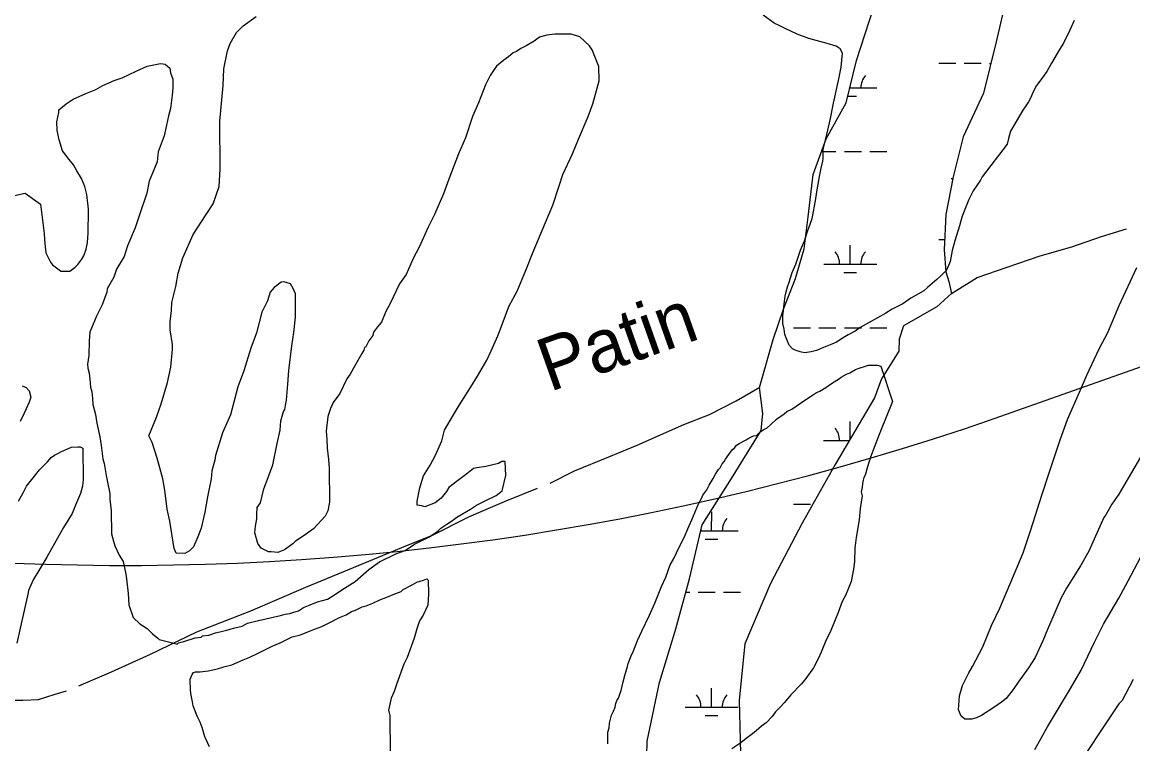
# Model space of a CAD drawing. Extents: x 3250478 to 3288318, y 788638 to 816472.
# Drawn here: x 3266413 to 3268510, y 804468 to 805829 of the extents above; entities that cross this region are included whole.
import ezdxf

# ---------------------------------------------------------------- set-up
doc = ezdxf.new("R2010")
doc.units = 0
for name, color, linetype in [('V-RIVR-IDEN', 7, 'Continuous'), ('V-ROAD-CNTR', 7, 'Continuous'), ('V-SITE-VEGE', 7, 'Continuous'), ('V-TOPO-SHOR', 7, 'Continuous'), ('V-WETL-SWMP', 7, 'Continuous')]:
    doc.layers.add(name, color=color, linetype=linetype)

msp = doc.modelspace()

# ---------------------------------------------------------------- linework, layer by layer
at = {"layer": 'V-ROAD-CNTR'}
msp.add_lwpolyline([(3268249.8, 805082), (3271535.1, 806242), (3280405.6, 809312.9)], dxfattribs=at)
msp.add_arc((3266606.2, 809804.1), 5000, 244.6063, 289.1908, dxfattribs=at)
at = {"layer": 'V-SITE-VEGE'}
for points in [[(3266694.3, 805285), (3266695.4, 805300.1), (3266702.5, 805330.3), (3266707.3, 805355.4), (3266715.7, 805384.3), (3266735.3, 805428.5), (3266759.9, 805466.4), (3266773.5, 805486.6), (3266784.4, 805519.3), (3266786.5, 805551.9), (3266785.5, 805642.2), (3266792.2, 805710), (3266793.1, 805741.4), (3266800.2, 805775.3), (3266805.1, 805789.2), (3266817.4, 805809.4), (3266829.8, 805822), (3266854.7, 805839.9)], [(3268187.3, 805463.4), (3268182.3, 805444.7), (3268173.8, 805416.7), (3268168.7, 805398.1), (3268164.5, 805377.7), (3268160.3, 805366.7), (3268156.9, 805359), (3268154.3, 805357.3), (3268147.6, 805351.4), (3268139.9, 805343.7), (3268122.1, 805328.4), (3268115.3, 805322.5), (3268090.7, 805308.1), (3268075.5, 805297.9), (3268055.1, 805287.7), (3268043.3, 805280), (3268011.9, 805262.2), (3267994.9, 805252.8), (3267985.6, 805246), (3267972, 805239.2), (3267962.7, 805233.3), (3267950, 805225.6), (3267941.5, 805221.4), (3267928.8, 805216.3), (3267925.4, 805215.4), (3267912.6, 805209.5), (3267902.5, 805206.9), (3267889.7, 805205.2), (3267881.3, 805206.9), (3267871.9, 805210.3), (3267866.8, 805212.9), (3267860.9, 805219.6), (3267857.5, 805227.3), (3267852.4, 805240), (3267851.5, 805250.2), (3267849, 805260.4), (3267849, 805274.8), (3267849.8, 805285.8), (3267851.5, 805296.8), (3267853.2, 805312.1), (3267854.9, 805320.6), (3267857.4, 805329.9), (3267860.8, 805338.4), (3267866.7, 805357.1), (3267873.5, 805372.4), (3267882, 805398.7), (3267889.6, 805416.5), (3267896.3, 805436), (3267900.6, 805447.9), (3267904, 805458.9), (3267906.5, 805471.7), (3267910.7, 805492), (3267913.3, 805509), (3267918.3, 805537.8), (3267920.9, 805554), (3267924.2, 805566.7), (3267925.1, 805571.8), (3267925.1, 805589.6), (3267930.1, 805609.1), (3267938.6, 805647.3), (3267944.5, 805676.2), (3267953.8, 805719.4), (3267958.9, 805744), (3267961.4, 805770.4), (3267957.2, 805778.8), (3267949.5, 805783.9), (3267932.5, 805789), (3267897.8, 805798.3), (3267875.7, 805806.8), (3267851.9, 805817.8), (3267843.4, 805822), (3267832.4, 805827.1), (3267812, 805842.3)], [(3268399.2, 805832.6), (3268390.7, 805814), (3268378.8, 805789.4), (3268371.2, 805777.5), (3268355.9, 805752), (3268347.5, 805735.9), (3268333.9, 805718), (3268328, 805709.6), (3268320.4, 805695.1), (3268317.8, 805688.3), (3268312.7, 805679), (3268307.6, 805671.4), (3268301.7, 805662.9), (3268278.8, 805623.8), (3268274.6, 805609.4), (3268272.1, 805599.2), (3268225.5, 805537.2), (3268222.1, 805531.3), (3268208.5, 805510.9), (3268200, 805494.8), (3268187.3, 805463.4)], [(3266989, 804740.4), (3266999, 804746.8), (3267021.4, 804760.9), (3267041.3, 804773.7), (3267067.3, 804796.5), (3267087.2, 804810.6), (3267118.4, 804826), (3267135.9, 804832.4), (3267153.3, 804843.9), (3267163.3, 804849.1), (3267182, 804858), (3267187, 804861.9), (3267193.2, 804865.7), (3267198.2, 804869.5), (3267203.1, 804874.6), (3267214.3, 804882.2), (3267223, 804887.4), (3267233, 804895), (3267259.1, 804910.3), (3267270.3, 804918), (3267286.6, 804925.7), (3267307.8, 804936), (3267318.9, 804944.9), (3267326.1, 804973.8), (3267324.6, 805000.1), (3267318.3, 805000.1), (3267312.1, 804996.2), (3267288.3, 804990.9), (3267270.8, 804988.2), (3267264.5, 804986.9), (3267252.1, 804976.7), (3267237.2, 804965.3), (3267218.5, 804951.3), (3267213.6, 804943.7), (3267203.7, 804931), (3267192.5, 804922.1), (3267172.6, 804914.4), (3267167.5, 804916.8), (3267158.7, 804918), (3267158.6, 804925.5), (3267163.4, 804950.6), (3267170.6, 804973.3), (3267182.9, 804993.5), (3267192.8, 805012.4), (3267205, 805038.9), (3267209.8, 805059), (3267227, 805088), (3267238.1, 805107), (3267259, 805139.8), (3267272.5, 805161.3), (3267289.8, 805191.6), (3267298.3, 805209.2), (3267310.5, 805237), (3267319.1, 805258.4), (3267331.2, 805292.4), (3267347.2, 805321.4), (3267363.1, 805359.2), (3267377.7, 805395.8), (3267400.9, 805451.2), (3267414.3, 805484), (3267426.4, 805520.5), (3267433.7, 805541.9), (3267452, 805581), (3267463, 805608.7), (3267481.3, 805651.5), (3267489.8, 805675.4), (3267501.9, 805718.2), (3267501.5, 805745.8), (3267488.6, 805777), (3267483.5, 805784.5), (3267465.8, 805801.8), (3267449.4, 805806.6), (3267418.1, 805806.3), (3267403.1, 805804.8), (3267389.3, 805800.9), (3267379.4, 805793.3), (3267364.4, 805784.3), (3267354.4, 805779.2), (3267345.7, 805774.1), (3267339.5, 805771.5), (3267330.8, 805763.9), (3267322.1, 805757.5), (3267308.4, 805746.1), (3267303.5, 805739.7), (3267296.1, 805728.4), (3267287.5, 805710.7), (3267274.1, 805676.7), (3267263.1, 805651.5), (3267249.8, 805611.2), (3267236.3, 805581), (3267218.1, 805533.1), (3267208.4, 805505.4), (3267191.3, 805466.3), (3267179, 805442.4), (3267161.9, 805404.5), (3267150.9, 805383.1), (3267137.4, 805352.9), (3267125.1, 805335.2), (3267106.7, 805297.3), (3267099.3, 805283.4), (3267090.8, 805263.3)], [(3266501.6, 805570), (3266488.9, 805586.1), (3266482.4, 805607.4), (3266478.4, 805624.9), (3266478.2, 805641.2), (3266481.8, 805658.8), (3266481.7, 805663.8), (3266495.4, 805675.2), (3266509.1, 805684.2), (3266532.8, 805694.5), (3266551.5, 805702.2), (3266565.2, 805709.9), (3266586.4, 805718.9), (3266601.4, 805724.1), (3266627.6, 805737), (3266648.8, 805746), (3266673.9, 805751.3), (3266682.6, 805750.1), (3266691.5, 805742.7), (3266692.9, 805733.9), (3266696.8, 805721.5), (3266697, 805705.2), (3266695.9, 805691.3), (3266692.4, 805666.2), (3266688.8, 805652.4), (3266685.2, 805634.8), (3266680.4, 805614.7), (3266669.5, 805584.5), (3266667.2, 805565.6), (3266652.6, 805529.1), (3266647.8, 805506.5), (3266634.5, 805467.4), (3266626, 805441), (3266611.4, 805407), (3266605.3, 805386.8), (3266590.6, 805362.8), (3266585.7, 805347.7), (3266573.4, 805326.3), (3266572.2, 805320), (3266563.7, 805296.1), (3266552.7, 805274.6), (3266540.5, 805244.4), (3266539.4, 805228.1), (3266538.5, 805200.5), (3266536.2, 805184.1), (3266536.3, 805176.6), (3266538.9, 805166.6), (3266540.3, 805155.4), (3266541.7, 805140.3), (3266544.3, 805131.6), (3266545.7, 805119), (3266545.9, 805107.8), (3266551.1, 805089), (3266553.8, 805072.7), (3266559.1, 805046.5), (3266561.8, 805030.2), (3266564.6, 805005.2), (3266567.2, 804996.4), (3266571.2, 804973.9), (3266573.9, 804961.4), (3266577.9, 804940.1), (3266578, 804928.8), (3266580.8, 804907.5), (3266581.3, 804863.6), (3266585.2, 804849.9), (3266587.8, 804841.2), (3266595.5, 804823.7), (3266603.2, 804811.2), (3266608.5, 804787.5), (3266609.8, 804778.7), (3266612.7, 804751.1), (3266614.2, 804729.8), (3266622, 804706.1), (3266634.7, 804693.7), (3266648.5, 804685.1), (3266658.7, 804675.2), (3266668.8, 804666.5), (3266671.4, 804664), (3266696.5, 804658.1), (3266705.3, 804655.7), (3266707.8, 804658.2), (3266717.8, 804660.8), (3266739, 804667.3), (3266750.3, 804668.7), (3266752.8, 804671.3), (3266765.3, 804672.7), (3266777.8, 804676.6), (3266799.1, 804681.8), (3266811.6, 804685.7), (3266827.8, 804689.7), (3266837.8, 804694.8), (3266859, 804700.1), (3266900.3, 804709.3), (3266909.1, 804711.9), (3266917.8, 804713.3), (3266925.3, 804715.9), (3266934.1, 804718.5), (3266944, 804724.9), (3266956.5, 804730), (3266970.2, 804735.2), (3266989, 804740.4)], [(3266398.3, 805502.3), (3266418.4, 805506.3), (3266447.1, 805485.7), (3266454.4, 805430.2), (3266454.5, 805419), (3266455.9, 805405.2), (3266457.3, 805393.9), (3266466.3, 805376.5), (3266470.1, 805371.5), (3266482.7, 805361.6), (3266485.3, 805359.1), (3266502.8, 805359.3), (3266512.8, 805367), (3266517.7, 805372), (3266525.1, 805382.1), (3266528.8, 805388.5), (3266533.7, 805401.1), (3266536.1, 805413.6), (3266537.1, 805431.2), (3266537, 805443.7), (3266538, 805461.3), (3266537.8, 805476.3), (3266535, 805503.9), (3266531.1, 805518.9), (3266524.6, 805533.9), (3266515.7, 805548.8), (3266509.3, 805560), (3266501.6, 805570)], [(3268530.5, 805019.1), (3268500.8, 804969), (3268483, 804938.5), (3268470.3, 804919.8), (3268458.4, 804899.4), (3268455.1, 804894.3), (3268426.3, 804830.7), (3268411, 804803.5), (3268394.1, 804776.3), (3268384.7, 804761.1), (3268374.6, 804743.2), (3268364.4, 804719.5), (3268348.3, 804683), (3268339.9, 804661.7), (3268325.5, 804630.3), (3268312.7, 804610.8), (3268293.2, 804583.7), (3268283.9, 804570.1), (3268270.4, 804553.1), (3268261.9, 804546.3), (3268249.2, 804537), (3268223.7, 804520.8), (3268214.4, 804516.6), (3268205.9, 804514), (3268192.3, 804514), (3268185.6, 804519.9), (3268180.4, 804531.8), (3268182.1, 804558.1), (3268188, 804577.6), (3268199.9, 804601.4), (3268206.7, 804613.3), (3268226.2, 804650.6), (3268243.1, 804690.5), (3268258.4, 804723.6), (3268284.6, 804784.7), (3268302.4, 804828), (3268316.8, 804871.3), (3268337.9, 804936.6), (3268351.5, 804979.1), (3268372.6, 805041), (3268386.2, 805079.2), (3268409, 805131), (3268422.6, 805163.2), (3268446.3, 805212.5), (3268462.4, 805243.9), (3268483.6, 805294.8), (3268517.5, 805366.1)], [(3267090.8, 805263.3), (3267083.4, 805254.4), (3267076, 805244.3), (3267074.8, 805238), (3267067.4, 805227.9), (3267062.5, 805219.1), (3267061.2, 805216.5), (3267058.7, 805215.3), (3267057.6, 805210.2), (3267053.9, 805203.9), (3267048.9, 805195.1), (3267037.9, 805176.1), (3267031.7, 805164.8), (3267025.6, 805155.9), (3267012.1, 805128.2), (3266999.8, 805111.8), (3266994.9, 805100.4), (3266990, 805085.3), (3266986.6, 805057.7), (3266988, 805042.6), (3266988.2, 805025.1), (3266991, 805003.8), (3266992.4, 804987.5), (3266993.1, 804923.6), (3266989.6, 804907.2), (3266984.7, 804897.1), (3266962.4, 804873.1), (3266945, 804860.3), (3266928.8, 804850.1), (3266923.8, 804845), (3266907.7, 804833.6), (3266895.2, 804828.4), (3266882.6, 804829.5), (3266877.6, 804829.4), (3266863.7, 804836.8), (3266857.4, 804845.5), (3266852.1, 804865.5), (3266853.2, 804878.1), (3266855.6, 804891.9), (3266855.5, 804900.7), (3266856.6, 804913.2), (3266862.7, 804922.1), (3266868.7, 804948.5), (3266877.2, 804969.9), (3266885.7, 804993.8), (3266894.1, 805034), (3266900, 805059.2), (3266901.1, 805076.8), (3266905.9, 805094.4), (3266908.4, 805098.2), (3266909.5, 805105.7), (3266911.9, 805115.8), (3266914.1, 805145.9), (3266916.3, 805172.2), (3266922, 805218.7), (3266925.5, 805243.8), (3266928.9, 805272.7), (3266928.4, 805316.6), (3266924.5, 805326.6), (3266919.4, 805335.3), (3266906.8, 805338.9), (3266901.8, 805338.8), (3266888.1, 805328.7), (3266880.7, 805319.8), (3266875.9, 805303.4), (3266864.9, 805282), (3266855.3, 805243), (3266844.3, 805214), (3266831, 805171.2), (3266820.1, 805141), (3266805.7, 805088.2), (3266791, 805054.2), (3266777.7, 805011.4), (3266776.5, 805002.6), (3266770.5, 804982.4), (3266769.4, 804967.4), (3266762.3, 804933.5), (3266757.6, 804904.6), (3266750.4, 804874.4), (3266744.4, 804858), (3266735.8, 804839.1), (3266728.4, 804831.5), (3266719.6, 804826.4), (3266703.3, 804827.4), (3266699.5, 804836.2), (3266691.4, 804887.5), (3266686.1, 804910), (3266681.9, 804946.3), (3266677.9, 804967.6), (3266667.4, 805006.3), (3266658.3, 805036.3), (3266651.9, 805048.8), (3266666.5, 805084.1), (3266675, 805109.3), (3266687.1, 805149.5), (3266693, 805178.4), (3266696.4, 805212.3), (3266696.3, 805221.1), (3266692.2, 805248.6), (3266692, 805263.7), (3266694.3, 805285)], [(3267698, 804936.5), (3267705.6, 804946.7), (3267709.8, 804955.2), (3267717.4, 804968), (3267721.7, 804976.4), (3267727.6, 804984.9), (3267730.2, 804988.3), (3267734.4, 804996), (3267737.8, 805000.2), (3267740.3, 805004.5), (3267753, 805022.3), (3267758.1, 805026.5), (3267761.5, 805030.8), (3267766.6, 805034.2), (3267775.9, 805039.3), (3267779.3, 805041), (3267783.6, 805043.5), (3267793.7, 805048.6), (3267798.8, 805049.5), (3267805.6, 805055.4), (3267811.5, 805059.7), (3267819.2, 805063.9), (3267826, 805069.9), (3267837, 805080), (3267851.4, 805090.2), (3267856.5, 805094.5), (3267865.8, 805098.7), (3267874.3, 805104.7), (3267892.1, 805117.4), (3267903.1, 805124.2), (3267912.5, 805130.2), (3267918.4, 805132.7), (3267930.3, 805139.5), (3267940.4, 805147.1), (3267955.7, 805156.5), (3267959.1, 805159), (3267969.3, 805165), (3267975.2, 805167.5), (3267986.2, 805173.5), (3267993, 805176), (3268004.9, 805180.3), (3268010.8, 805182), (3268027, 805182), (3268033.7, 805180.3), (3268055.9, 805113.3)], [(3266412.3, 805143), (3266420.4, 805139.6), (3266425.9, 805133.4), (3266428.7, 805121.8), (3266426.1, 805111.9), (3266420, 805099.3), (3266416.5, 805091.2), (3266408.6, 805075.9)], [(3268055.9, 805113.3), (3268041.5, 805077.7), (3268037.2, 805066.6), (3268030.5, 805051.3), (3268014.4, 805008.1), (3268008.4, 804990.2), (3268004.2, 804974.1), (3268001.7, 804969.9), (3268000.8, 804964.8), (3267999.1, 804958.8), (3267998.3, 804951.2), (3267996.6, 804942.7), (3267998.3, 804935.1), (3267994.9, 804911.3), (3267993.2, 804890.1), (3267987.3, 804857), (3267984.8, 804836.7), (3267984, 804811.2), (3267982.3, 804796.8), (3267978.1, 804773.9), (3267973, 804761.1), (3267967.1, 804747.6), (3267961.1, 804735.7), (3267953.5, 804715.3), (3267947.6, 804701.7), (3267938.3, 804678), (3267930.6, 804663.5), (3267921.3, 804640.6), (3267915.4, 804627.9), (3267906.9, 804610.9), (3267892.5, 804590.5), (3267884.1, 804580.4), (3267863.7, 804560), (3267851.8, 804545.5), (3267843.4, 804536.2), (3267834.9, 804527.7), (3267828.9, 804519.2), (3267817.1, 804507.3), (3267808.6, 804500.5), (3267798.4, 804492), (3267791.6, 804486.1), (3267779.8, 804477.6), (3267769.6, 804469.1), (3267752.6, 804458.1)], [(3266405.9, 804925.6), (3266414.7, 804940.9), (3266420.8, 804953.5), (3266435.8, 804972.5), (3266445.5, 804984.2), (3266460.5, 804999.6), (3266467.5, 805007.7), (3266473.8, 805012.3), (3266480.9, 805015.9), (3266485.3, 805018.7), (3266496.9, 805023.3), (3266505.8, 805027), (3266517.4, 805028), (3266521.9, 805028), (3266527.3, 805025.4), (3266527.9, 804966.4), (3266526.3, 804953.9), (3266522.9, 804939.5), (3266513.3, 804917.9), (3266507.2, 804901.8), (3266490.5, 804875.6), (3266467.8, 804835.1), (3266459, 804819.8), (3266444.1, 804794.6), (3266433.5, 804776.6), (3266424.8, 804756.8), (3266423.1, 804749.7), (3266402.7, 804657.3)], [(3267518.5, 804467.2), (3267518.4, 804489.3), (3267521, 804497.8), (3267521.8, 804506.2), (3267525.2, 804521.5), (3267529.4, 804529.2), (3267532, 804536.8), (3267533.7, 804543.6), (3267536.2, 804550.4), (3267538.8, 804553.8), (3267541.3, 804561.4), (3267543.8, 804568.2), (3267547.2, 804584.3), (3267550.6, 804596.2), (3267555.7, 804613.2), (3267556.5, 804619.1), (3267562.5, 804633.5), (3267566.7, 804642.9), (3267574.3, 804662.4), (3267582.8, 804680.2), (3267597.2, 804709.9), (3267607.3, 804732.8), (3267620, 804764.2), (3267627.7, 804782.1), (3267636.1, 804805), (3267642.1, 804816), (3267648, 804827.9), (3267652.2, 804837.2), (3267662.4, 804856.8), (3267669.2, 804872.9), (3267676.8, 804889.9), (3267689.5, 804920.4), (3267695.4, 804930.6), (3267698, 804936.5)], [(3268324.7, 804456.4), (3268348.5, 804499.7), (3268391.7, 804571.9), (3268412, 804606.7), (3268437.4, 804659.3), (3268454.4, 804693.2), (3268483.2, 804742.5), (3268501, 804774.7), (3268542.5, 804853.7)], [(3267104.3, 804745.5), (3267113, 804749.4), (3267128, 804754.6), (3267131.7, 804758.4), (3267149.2, 804767.4), (3267157.9, 804772.5), (3267170.4, 804776.4), (3267176.6, 804779), (3267179.2, 804776.5), (3267179.5, 804750.2), (3267178.5, 804728.8), (3267169.9, 804709.9), (3267162.5, 804699.8), (3267157.7, 804684.7), (3267152.9, 804667.1), (3267139.5, 804630.6), (3267133.4, 804618), (3267120, 804581.5), (3267115.1, 804566.3), (3267109, 804553.7), (3267104.3, 804531.1), (3267106.9, 804521.1), (3267107.7, 804449.6)], [(3266766.5, 804462), (3266758.8, 804478.2), (3266757.5, 804480.7), (3266752.3, 804498.2), (3266748.4, 804508.2), (3266743.3, 804519.4), (3266735.5, 804539.4), (3266734.2, 804546.9), (3266731.5, 804559.4), (3266730.2, 804568.2), (3266729.9, 804589.5), (3266733.6, 804598.3), (3266736, 804602.1), (3266739.8, 804603.4), (3266748.6, 804603.5), (3266763.6, 804604.9), (3266781.1, 804608.9), (3266793.6, 804612.8), (3266808.6, 804616.7), (3266818.6, 804620.6), (3266829.8, 804625.8), (3266842.3, 804630.9), (3266858.5, 804638.6), (3266884.7, 804651.5), (3266899.7, 804657.9), (3266922.1, 804669.5), (3266938.4, 804673.4), (3266952.1, 804678.6), (3266964.6, 804683.7), (3266978.3, 804688.9), (3266990.8, 804695.3), (3267012, 804705.6), (3267024.4, 804710.8), (3267034.4, 804717.1), (3267041.9, 804719.7), (3267054.4, 804726.2), (3267061.9, 804727.5), (3267074.4, 804732.7), (3267088.1, 804739.1), (3267104.3, 804745.5)], [(3268510.4, 804588.9), (3268496, 804560.9), (3268489.3, 804549), (3268483.3, 804543.1), (3268391, 804403.9)]]:
    msp.add_lwpolyline(points, dxfattribs=at)
at = {"layer": 'V-TOPO-SHOR'}
for points in [[(3268167.5, 805317.1), (3268215.8, 805347.3), (3268272.1, 805366.9), (3268334.6, 805388.1), (3268394.7, 805405.5), (3268450.4, 805424.5), (3268497.6, 805439)], [(3267409.6, 804959.6), (3267455.4, 804982.8), (3267520.5, 805009.2), (3267573.6, 805030.7), (3267661.9, 805070.2), (3267710.3, 805089.1), (3267760.6, 805114.5), (3267805.5, 805140.3)], [(3266519.5, 804576.6), (3266581.5, 804603), (3266654.8, 804636.7), (3266742.7, 804678.5), (3266844.2, 804718.3), (3266948.4, 804763), (3267048.7, 804804.3), (3267139.9, 804842.3), (3267186, 804860.4), (3267257, 804896.4), (3267323.1, 804925), (3267385.4, 804950.1)], [(3265889.8, 804295.3), (3265944, 804327.2), (3265976.4, 804351.4), (3266020.3, 804383.9), (3266060.3, 804401.8), (3266093.9, 804415.6), (3266122.5, 804431.8), (3266150.8, 804454.2), (3266175.3, 804475.6), (3266216.6, 804505.2), (3266259.8, 804530.2), (3266278, 804538.8), (3266297.9, 804544), (3266333.1, 804547.8), (3266376.8, 804549.5), (3266414, 804549.5), (3266443.2, 804551.2), (3266474.7, 804561.3), (3266496, 804567.5)]]:
    msp.add_lwpolyline(points, dxfattribs=at)
at = {"layer": 'V-WETL-SWMP'}
for p, q in [((3268143.2, 805751.6), (3268175.2, 805751.6)), ((3268191.2, 805751.6), (3268223.2, 805751.6)), ((3268239.2, 805751.5), (3268241.5, 805751.5)), ((3267975.2, 805705.2), (3268026.1, 805705.2)), ((3267976.1, 805705.2), (3267976.1, 805708.9)), ((3267971.6, 805689.8), (3267988.1, 805689.8)), ((3267922.1, 805585.1), (3267949.2, 805585.1)), ((3267965.2, 805585.1), (3267997.2, 805585.1)), ((3268013.2, 805585.1), (3268045.2, 805585.1)), ((3268166.5, 805534.3), (3268169.9, 805534.3)), ((3268143.1, 805418.9), (3268154.5, 805418.9)), ((3267976, 805372.5), (3267976, 805408.5)), ((3267926, 805372.5), (3268026, 805372.5)), ((3267964, 805357.1), (3267988, 805357.1)), ((3267869.1, 805252.5), (3267901.1, 805252.5)), ((3267917.1, 805252.5), (3267949.1, 805252.5)), ((3267965.1, 805252.5), (3267997.1, 805252.4)), ((3268013.1, 805252.4), (3268045.1, 805252.4)), ((3267975.9, 805042.6), (3267975.9, 805075.8)), ((3267925.9, 805039.9), (3267974.3, 805039.8)), ((3267963.9, 805024.4), (3267965.2, 805024.4)), ((3267869, 804919.8), (3267901, 804919.8)), ((3267714.4, 804869.1), (3267714.5, 804905.1)), ((3267693.7, 804869.1), (3267764.4, 804869.1)), ((3267702.4, 804853.7), (3267726.4, 804853.7)), ((3267665.8, 804753.7), (3267673, 804753.7)), ((3267689, 804753.7), (3267721, 804753.7)), ((3267737, 804753.7), (3267769, 804753.7)), ((3267714.3, 804536.4), (3267714.4, 804572.4)), ((3267664.3, 804536.5), (3267764.3, 804536.4)), ((3267702.3, 804521), (3267726.3, 804521))]:
    msp.add_line(p, q, dxfattribs=at)
for points in [[(3267804.9, 805139.9), (3267830.4, 805230.1), (3267849.9, 805287.9), (3267872.8, 805345.5), (3267888.9, 805401.7), (3267896.6, 805462), (3267906.1, 805541.6), (3267930.7, 805608.8), (3267968.6, 805677.2), (3267987.6, 805757.1), (3268012.2, 805832.5), (3268036.7, 805908.1), (3268055.8, 805993.8), (3268074.8, 806090.1), (3268091.2, 806169.9), (3268117.3, 806238.6), (3268159.3, 806311.3), (3268181.7, 806419.8), (3268212.9, 806532.8), (3268243.3, 806630.5), (3268265.1, 806718.6), (3268304.4, 806801.7), (3268334.2, 806861.3)], [(3268271.7, 805879.5), (3268251.5, 805792.3), (3268227.6, 805695.2), (3268189.1, 805612.6), (3268170.5, 805537.6), (3268156.8, 805466), (3268153.6, 805399.8), (3268156.8, 805358.3), (3268162, 805340.1), (3268167.5, 805317.1), (3268139.4, 805292.2), (3268076.6, 805255.9), (3268068.6, 805230.8), (3268068, 805208.5), (3268035.1, 805156.2), (3268021.8, 805120.6), (3267947.7, 804994.7), (3267885.2, 804883.6), (3267825.3, 804769.7), (3267777.3, 804655.9), (3267766.5, 804550.1), (3267768, 804474.2), (3267768.6, 804448.4)], [(3267592.1, 804444.9), (3267592.5, 804472.2), (3267616, 804583.1), (3267646.8, 804684.2), (3267672.6, 804778.6), (3267696.4, 804880.7), (3267751.7, 804967.8), (3267808, 805058.6), (3267810.9, 805090.9), (3267804.9, 805139.9)]]:
    msp.add_lwpolyline(points, dxfattribs=at)
for centre, start, end in [((3268031.4, 805705.7), 139.2115, 180.7552), ((3267920.8, 805373), 359.2115, 40.7552), ((3268031.3, 805373), 139.2115, 180.7552), ((3267920.7, 805040.3), 359.2115, 40.7552), ((3267769.7, 804869.6), 139.2115, 180.7552), ((3267659.2, 804869.6), 359.2115, 4.001), ((3267659.1, 804536.9), 359.2115, 40.7552), ((3267769.6, 804536.9), 139.2115, 180.7552)]:
    msp.add_arc(centre, 35.2, start, end, dxfattribs=at)

# ---------------------------------------------------------------- texts
at = {"layer": 'V-RIVR-IDEN'}
msp.add_text('Patin', height=100, rotation=19.5127, dxfattribs=at).set_placement((3267408.2, 805131))

doc.saveas('drawing.dxf')
